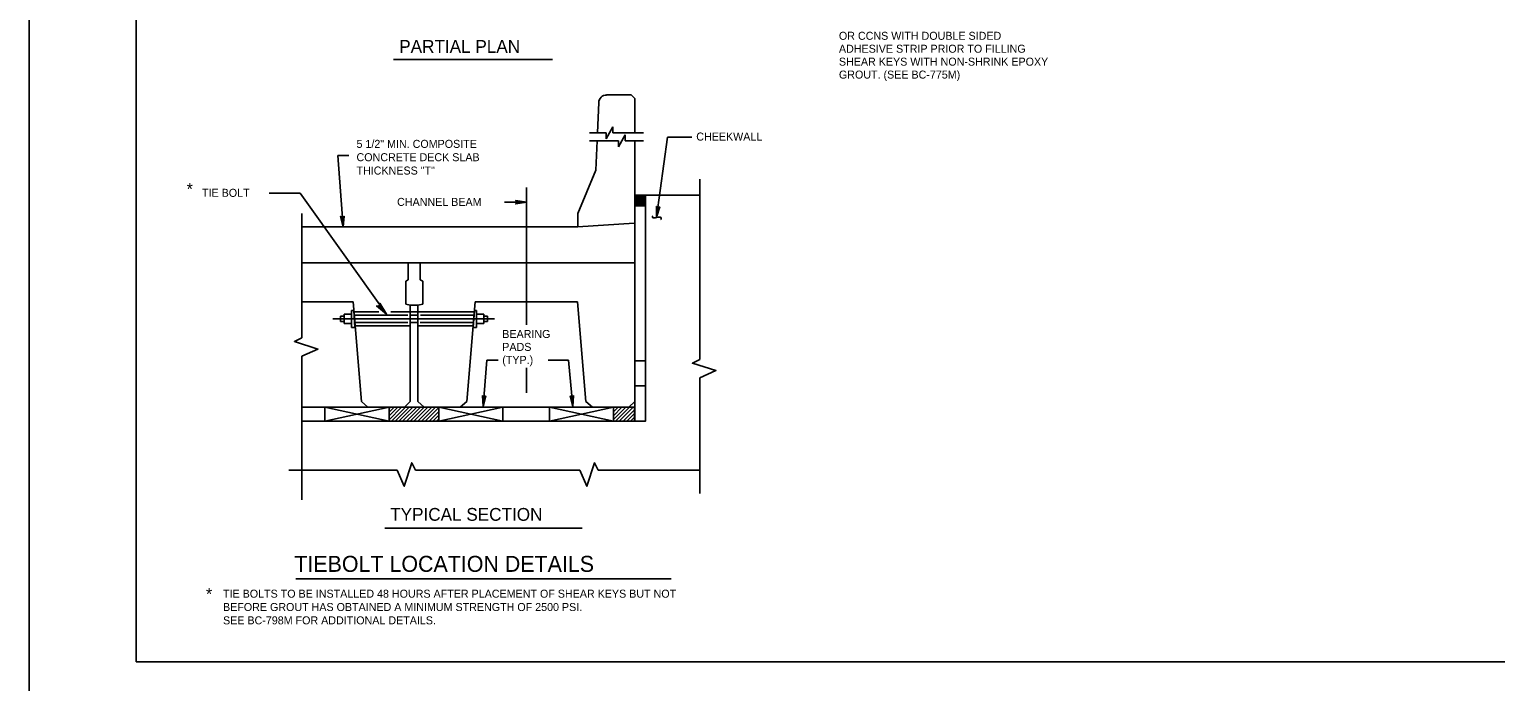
# Model space of a CAD drawing. Extents: x 642009 to 642864, y 298232 to 300014.
# Drawn here: x 642009 to 642558, y 298833 to 299078 of the extents above; entities that cross this region are included whole.
import ezdxf

# ---------------------------------------------------------------- set-up
doc = ezdxf.new("R2010")
doc.units = 0
for name, color, linetype in [('1', 7, 'Continuous'), ('2', 7, 'Continuous'), ('3', 7, 'Continuous'), ('40', 7, 'Continuous'), ('PLT-BNDY', 7, 'Continuous')]:
    doc.layers.add(name, color=color, linetype=linetype)

msp = doc.modelspace()

# ---------------------------------------------------------------- linework, layer by layer
at = {"layer": '1'}
for p, q in [((642222.11, 299050.49), (642221.65, 299039.09)), ((642225.07, 299053.34), (642234.32, 299053.34)), ((642235.6, 299052.06), (642234.32, 299053.34)), ((642235.6, 299039.09), (642235.6, 299052.06)), ((642221.52, 299036.15), (642221.07, 299025.15)), ((642221.07, 299025.15), (642214.22, 299008.95)), ((642235.6, 299015.75), (642260.04, 299015.75)), ((642214.22, 299008.95), (642214.22, 299003.9)), ((642130.25, 298972.56), (642130.72, 298966.18)), ((642175.57, 298972.56), (642175.1, 298966.18))]:
    msp.add_line(p, q, dxfattribs=at)
msp.add_lwpolyline([(642140.01, 298974.92), (642139.88, 298974.57), (642142.6, 298971.14), (642140.01, 298974.92), (642140.01, 298975.23), (642142.6, 298971.14), (642139.54, 298974.27), (642139.19, 298974.17), (642142.6, 298971.14), (642138.86, 298974.21), (642139.19, 298974.17)], dxfattribs=at)
msp.add_lwpolyline([(642151.47, 298972.04), (642154.35, 298972.04), (642154.35, 298974.54), (642151.47, 298974.54)], close=True, dxfattribs=at)
msp.add_arc((642225.07, 299050.37), 2.96, 90, 177.65, dxfattribs=at)
at = {"layer": '2'}
for p, q in [((642048.66, 298840.82), (642048.66, 299404.82)), ((642204.78, 299066.65), (642145.19, 299066.65)), ((642218.65, 299039.09), (642224.84, 299039.09)), ((642227.44, 299039.09), (642238.9, 299039.09)), ((642218.65, 299036.15), (642229.46, 299036.15)), ((642232.06, 299036.15), (642238.9, 299036.15)), ((642235.6, 299036.15), (642235.6, 298930.99)), ((642194.97, 299018.62), (642194.97, 298967.12)), ((642260.04, 299021.8), (642260.04, 298954.18)), ((642110.17, 299016.5), (642098.59, 299016.5)), ((642142.6, 298971.14), (642110.17, 299016.5)), ((642239.6, 299015.75), (642239.6, 298930.99)), ((642110.85, 299008.87), (642110.85, 298962.25)), ((642214.22, 299003.9), (642110.85, 299003.9)), ((642235.37, 299005.26), (642214.22, 299003.9)), ((642155.17, 298990.4), (642110.85, 298990.4)), ((642150.65, 298990.4), (642150.65, 298983.97)), ((642150.65, 298990.4), (642150.65, 298983.97)), ((642155.17, 298990.4), (642155.17, 298983.97)), ((642235.6, 298990.4), (642155.17, 298990.4)), ((642150.65, 298983.97), (642149.83, 298983.56)), ((642155.17, 298983.97), (642156.12, 298983.56)), ((642149.83, 298983.56), (642149.83, 298974.95)), ((642156.12, 298983.56), (642156.12, 298974.95)), ((642130, 298975.77), (642110.85, 298975.77)), ((642130, 298975.77), (642133.14, 298938.42)), ((642149.83, 298974.95), (642151.47, 298974.54)), ((642151.47, 298974.54), (642151.47, 298938.42)), ((642151.47, 298974.54), (642151.47, 298938.42)), ((642156.12, 298974.95), (642154.35, 298974.54)), ((642154.35, 298974.54), (642154.35, 298938.42)), ((642175.82, 298975.77), (642172.68, 298938.42)), ((642214.12, 298975.77), (642175.82, 298975.77)), ((642214.12, 298975.77), (642217.27, 298938.42)), ((642183.05, 298969.42), (642122.42, 298969.42)), ((642130.31, 298972.02), (642139.7, 298972.02)), ((642130.39, 298970.78), (642150.6, 298970.78)), ((642130.67, 298967.97), (642150.53, 298967.97)), ((642144.15, 298972.02), (642175.51, 298972.02)), ((642151.42, 298967.97), (642154.3, 298967.97)), ((642151.55, 298970.78), (642154.3, 298970.78)), ((642155.21, 298967.97), (642175.21, 298967.97)), ((642155.29, 298970.78), (642175.43, 298970.78)), ((642175.92, 298969.42), (642179.85, 298969.42)), ((642130.71, 298966.73), (642151.42, 298966.73)), ((642154.3, 298966.73), (642175.11, 298966.73)), ((642110.85, 298955.34), (642110.85, 298901.56)), ((642184.47, 298953.87), (642180.22, 298953.87)), ((642194.97, 298951), (642194.97, 298941.62)), ((642210.76, 298953.87), (642203.12, 298953.87)), ((642235.6, 298953.61), (642239.6, 298953.61)), ((642260.04, 298947.27), (642260.04, 298903.85)), ((642110.85, 298936.24), (642149.29, 298936.24)), ((642119.49, 298936.24), (642119.49, 298930.99)), ((642143.51, 298930.99), (642119.49, 298936.24)), ((642119.49, 298930.99), (642143.51, 298936.24)), ((642133.14, 298938.42), (642135.61, 298936.24)), ((642133.14, 298938.42), (642135.61, 298936.24)), ((642143.51, 298936.24), (642143.51, 298930.99)), ((642143.51, 298935.79), (642143.96, 298936.24)), ((642143.51, 298934.37), (642145.37, 298936.24)), ((642143.51, 298932.96), (642146.79, 298936.24)), ((642143.51, 298931.54), (642148.2, 298936.24)), ((642144.37, 298930.99), (642149.62, 298936.24)), ((642145.78, 298930.99), (642151.03, 298936.24)), ((642147.19, 298930.99), (642152.44, 298936.24)), ((642148.61, 298930.99), (642153.86, 298936.24)), ((642151.47, 298938.42), (642149.29, 298936.24)), ((642150.02, 298930.99), (642155.27, 298936.24)), ((642151.44, 298930.99), (642156.69, 298936.24)), ((642152.85, 298930.99), (642158.1, 298936.24)), ((642154.26, 298930.99), (642159.51, 298936.24)), ((642154.35, 298938.42), (642156.67, 298936.24)), ((642155.68, 298930.99), (642160.93, 298936.24)), ((642156.67, 298936.24), (642235.55, 298936.24)), ((642157.09, 298930.99), (642162.2, 298936.09)), ((642158.51, 298930.99), (642162.2, 298934.68)), ((642162.2, 298936.24), (642162.2, 298930.99)), ((642186.21, 298930.99), (642162.2, 298936.24)), ((642162.2, 298930.99), (642186.21, 298936.24)), ((642172.68, 298938.42), (642170.21, 298936.24)), ((642186.21, 298936.24), (642186.21, 298930.99)), ((642203.62, 298936.24), (642203.62, 298930.99)), ((642203.62, 298930.99), (642227.63, 298936.24)), ((642227.63, 298930.99), (642203.62, 298936.24)), ((642217.27, 298938.42), (642219.73, 298936.24)), ((642227.63, 298936.24), (642227.63, 298930.99)), ((642227.63, 298935.87), (642228, 298936.24)), ((642227.63, 298934.46), (642229.41, 298936.24)), ((642227.63, 298933.04), (642230.83, 298936.24)), ((642227.63, 298931.63), (642232.24, 298936.24)), ((642228.4, 298930.99), (642233.65, 298936.24)), ((642229.82, 298930.99), (642235.07, 298936.24)), ((642231.23, 298930.99), (642235.55, 298935.3)), ((642235.6, 298938.42), (642233.41, 298936.24)), ((642110.85, 298930.99), (642162.2, 298930.99)), ((642119.49, 298930.99), (642143.51, 298930.99)), ((642159.92, 298930.99), (642162.2, 298933.26)), ((642161.34, 298930.99), (642162.2, 298931.85)), ((642162.2, 298930.99), (642203.62, 298930.99)), ((642203.62, 298930.99), (642239.6, 298930.99)), ((642232.65, 298930.99), (642235.55, 298933.89)), ((642234.06, 298930.99), (642235.55, 298932.47)), ((642235.48, 298930.99), (642235.55, 298931.06)), ((642105.92, 298912.59), (642146.5, 298912.59)), ((642153.41, 298912.59), (642215, 298912.59)), ((642221.91, 298912.59), (642260.04, 298912.59)), ((642215.91, 298890.92), (642141.89, 298890.92)), ((642249.31, 298871.86), (642108.56, 298871.86)), ((642834.66, 298840.82), (642048.66, 298840.82))]:
    msp.add_line(p, q, dxfattribs=at)
for points in [[(642110.85, 298955.34), (642116.85, 298958.03), (642108.04, 298960.84), (642110.85, 298962.25)], [(642260.04, 298947.27), (642266.04, 298949.96), (642257.22, 298952.77), (642260.04, 298954.18)], [(642146.5, 298912.59), (642149.19, 298906.59), (642152, 298915.4), (642153.41, 298912.59)], [(642215, 298912.59), (642217.69, 298906.59), (642220.5, 298915.4), (642221.91, 298912.59)]]:
    msp.add_lwpolyline(points, dxfattribs=at)
for points in [[(642239.6, 298953.61), (642235.6, 298953.61), (642235.6, 298930.99), (642239.6, 298930.99)], [(642143.51, 298936.24), (642162.2, 298936.24), (642162.2, 298930.99), (642143.51, 298930.99)], [(642143.51, 298936.24), (642162.2, 298936.24), (642162.2, 298930.99), (642143.51, 298930.99)], [(642186.21, 298936.24), (642203.62, 298936.24), (642203.62, 298930.99), (642186.21, 298930.99)], [(642186.21, 298936.24), (642203.62, 298936.24), (642203.62, 298930.99), (642186.21, 298930.99)], [(642235.55, 298936.24), (642227.63, 298936.24), (642227.63, 298930.99), (642235.55, 298930.99)]]:
    msp.add_lwpolyline(points, close=True, dxfattribs=at)
msp.add_spline([(642245.32, 299006.68), (642245.55, 299006.9), (642245.54, 299007.21), (642245.5, 299007.35), (642245.28, 299007.52), (642244.97, 299007.57), (642242.82, 299007.25), (642242.45, 299007.32), (642242.28, 299007.41), (642242.25, 299007.61), (642242.22, 299007.8), (642242.23, 299007.86), (642242.38, 299008.03)], degree=3, dxfattribs=at)
at = {"layer": '3'}
for p, q in [((642243.8, 299007.5), (642247.94, 299037.5)), ((642247.94, 299037.5), (642257.05, 299037.5)), ((642126.3, 299003.87), (642124.25, 299030.63)), ((642124.25, 299030.63), (642128.48, 299030.63)), ((642186.8, 299013.12), (642194.97, 299013.12)), ((642235.6, 299015.5), (642239.6, 299015.5)), ((642235.6, 299015.25), (642239.6, 299015.25)), ((642235.6, 299015), (642239.6, 299015)), ((642235.6, 299014.75), (642239.6, 299014.75)), ((642235.6, 299014.5), (642239.6, 299014.5)), ((642235.6, 299014.25), (642239.6, 299014.25)), ((642235.6, 299014), (642239.6, 299014)), ((642235.6, 299013.75), (642239.6, 299013.75)), ((642235.6, 299013.5), (642239.6, 299013.5)), ((642235.6, 299013.25), (642239.6, 299013.25)), ((642235.6, 299013), (642239.6, 299013)), ((642235.6, 299012.75), (642239.6, 299012.75)), ((642235.6, 299012.5), (642239.6, 299012.5)), ((642235.6, 299012.25), (642239.6, 299012.25)), ((642235.6, 299012), (642239.6, 299012)), ((642235.6, 299011.75), (642239.6, 299011.75)), ((642125.35, 298968.39), (642125.35, 298970.35)), ((642126.73, 298970.35), (642125.35, 298970.35)), ((642126.73, 298968.39), (642125.35, 298968.39)), ((642126.73, 298967.62), (642126.73, 298971.12)), ((642129.49, 298971.12), (642126.73, 298971.12)), ((642129.49, 298967.62), (642126.73, 298967.62)), ((642129.49, 298966.18), (642129.49, 298972.56)), ((642130.25, 298972.56), (642129.49, 298972.56)), ((642175.57, 298972.56), (642176.33, 298972.56)), ((642176.33, 298966.18), (642176.33, 298972.56)), ((642176.33, 298971.12), (642179.09, 298971.12)), ((642176.33, 298967.62), (642179.09, 298967.62)), ((642179.09, 298967.62), (642179.09, 298971.12)), ((642179.09, 298970.35), (642180.47, 298970.35)), ((642179.09, 298968.39), (642180.47, 298968.39)), ((642180.47, 298968.39), (642180.47, 298970.35)), ((642130.72, 298966.18), (642129.49, 298966.18)), ((642175.1, 298966.18), (642176.33, 298966.18)), ((642178.8, 298936.5), (642180.22, 298953.87)), ((642212.42, 298936.5), (642210.76, 298953.87))]:
    msp.add_line(p, q, dxfattribs=at)
for points in [[(642191.19, 299013.6), (642191.33, 299013.32), (642194.97, 299013.12), (642191.19, 299013.6), (642191, 299013.76), (642194.97, 299013.12), (642191.34, 299012.94), (642191.2, 299012.67), (642194.97, 299013.12), (642191, 299012.49), (642191.2, 299012.67)], [(642244.79, 299011.18), (642244.5, 299011.08), (642243.8, 299007.5), (642244.79, 299011.18), (642244.98, 299011.35), (642243.8, 299007.5), (642244.12, 299011.13), (642243.87, 299011.3), (642243.8, 299007.5), (642243.72, 299011.53), (642243.87, 299011.3)], [(642126.48, 299007.69), (642126.22, 299007.52), (642126.3, 299003.87), (642126.48, 299007.69), (642126.63, 299007.89), (642126.3, 299003.87), (642125.84, 299007.49), (642125.56, 299007.6), (642126.3, 299003.87), (642125.36, 299007.79), (642125.56, 299007.6)], [(642179.58, 298940.23), (642179.3, 298940.12), (642178.8, 298936.5), (642179.58, 298940.23), (642179.76, 298940.41), (642178.8, 298936.5), (642178.92, 298940.14), (642178.66, 298940.3), (642178.8, 298936.5), (642178.49, 298940.52), (642178.66, 298940.3)], [(642212.54, 298940.31), (642212.28, 298940.15), (642212.42, 298936.5), (642212.54, 298940.31), (642212.68, 298940.52), (642212.42, 298936.5), (642211.9, 298940.11), (642211.61, 298940.21), (642212.42, 298936.5), (642211.41, 298940.4), (642211.61, 298940.21)]]:
    msp.add_lwpolyline(points, dxfattribs=at)
msp.add_lwpolyline([(642235.6, 298944.24), (642239.6, 298944.24), (642239.6, 299015.75), (642235.6, 299015.75)], close=True, dxfattribs=at)
at = {"layer": '40'}
for p, q in [((642224.84, 299036.84), (642226.14, 299039.09)), ((642224.84, 299036.84), (642224.84, 299039.09)), ((642226.14, 299039.09), (642227.44, 299041.34)), ((642227.44, 299039.09), (642227.44, 299041.34)), ((642229.46, 299033.9), (642230.76, 299036.15)), ((642229.46, 299033.9), (642229.46, 299036.15)), ((642230.76, 299036.15), (642232.06, 299038.4)), ((642232.06, 299036.15), (642232.06, 299038.4))]:
    msp.add_line(p, q, dxfattribs=at)
at = {"layer": 'PLT-BNDY'}
msp.add_lwpolyline([(642008.66, 299419.82), (642849.66, 299419.82), (642849.66, 298825.82), (642008.66, 298825.82)], close=True, dxfattribs=at)

# ---------------------------------------------------------------- texts
at = {"layer": '1'}
for p in [(642067.63, 299015.84), (642074.87, 298863.93)]:
    msp.add_text('*', height=4.5, dxfattribs=at).set_placement(p)
at = {"layer": '2'}
for s, height, p in [('OR CCNS WITH DOUBLE SIDED ', 3, (642312.15, 299074.04)), ('PARTIAL PLAN', 4.8, (642147.33, 299069.15)), ('ADHESIVE STRIP PRIOR TO FILLING ', 3, (642312.15, 299069.19)), ('SHEAR KEYS WITH NON-SHRINK EPOXY ', 3, (642312.15, 299064.34)), ('GROUT. (SEE BC-775M)', 3, (642312.15, 299059.49)), ('5 1/2" MIN. COMPOSITE', 3, (642131.31, 299033.51)), ('CONCRETE DECK SLAB', 3, (642131.31, 299028.51)), ('THICKNESS "T"', 3, (642131.31, 299023.51)), ('TIE BOLT ', 3, (642073.41, 299015.15)), ('BEARING', 3, (642185.95, 298962.22)), ('PADS', 3, (642185.95, 298957.37)), ('(TYP.)', 3, (642185.95, 298952.52)), ('TYPICAL SECTION', 4.8, (642143.94, 298893.66)), ('TIEBOLT LOCATION DETAILS', 6, (642108, 298874.51)), ('TIE BOLTS TO BE INSTALLED 48 HOURS AFTER PLACEMENT OF SHEAR KEYS BUT NOT', 3, (642081.27, 298864.82)), ('BEFORE GROUT HAS OBTAINED A MINIMUM STRENGTH OF 2500 PSI.', 3, (642081.27, 298859.82)), ('SEE BC-798M FOR ADDITIONAL DETAILS.', 3, (642081.27, 298854.82))]:
    msp.add_text(s, height=height, dxfattribs=at).set_placement(p)
at = {"layer": '3'}
for s, p in [('CHEEKWALL', (642258.67, 299036.25)), ('  CHANNEL BEAM', (642144.3, 299011.75))]:
    msp.add_text(s, height=3, dxfattribs=at).set_placement(p)

doc.saveas('drawing.dxf')
